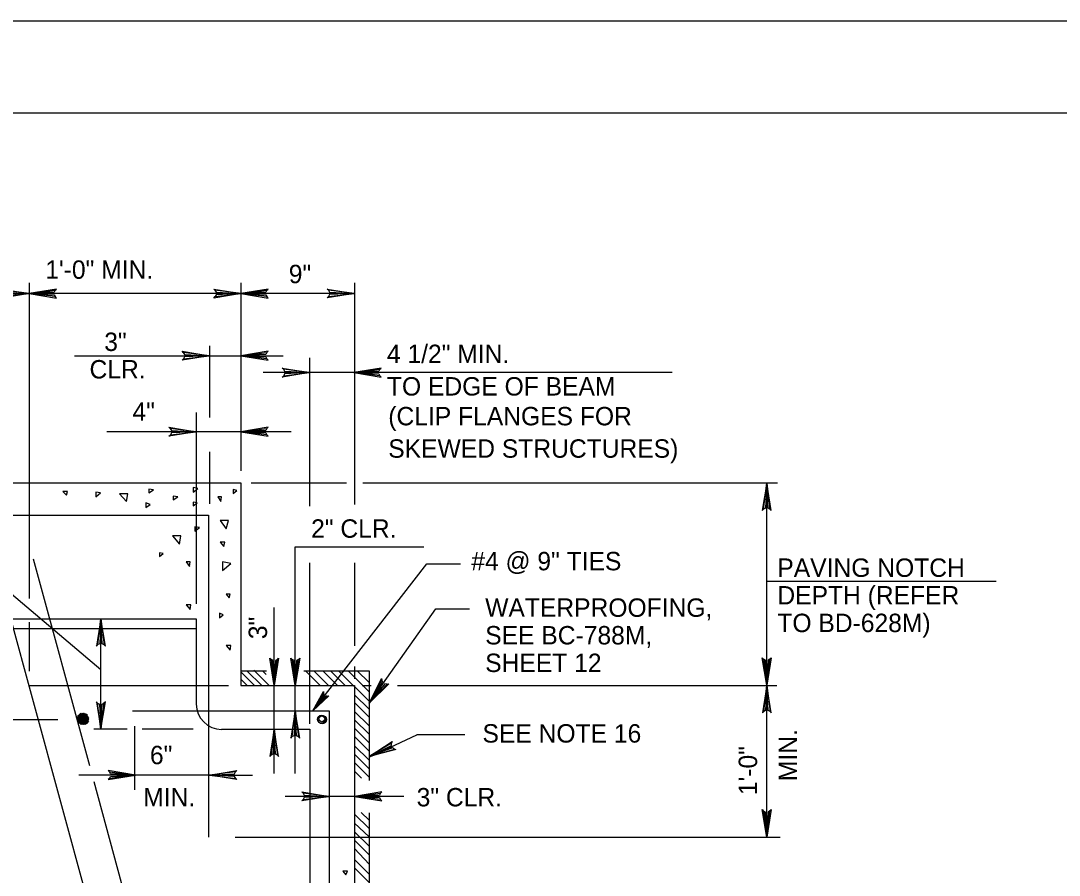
# Model space of a CAD drawing. Extents: x 640009 to 641706, y 298547 to 299735.
# Drawn here: x 640461.6 to 640630.8, y 299595.9 to 299735.2 of the extents above; entities that cross this region are included whole.
import ezdxf

# ---------------------------------------------------------------- set-up
doc = ezdxf.new("R2010")
doc.units = 0
doc.layers.add('1', color=7, linetype='Continuous')
doc.layers.add('PLT-BNDY', color=7, linetype='Continuous')

msp = doc.modelspace()

# ---------------------------------------------------------------- linework, layer by layer
at = {"layer": '1'}
for p, q in [((640049.47, 299720.17), (640835.47, 299720.17)), ((640049.47, 299720.17), (640835.47, 299720.17)), ((640462.97, 299692.45), (640462.97, 299640.98)), ((640497.47, 299692.45), (640497.47, 299661.83)), ((640515.97, 299692.45), (640515.97, 299656.35)), ((640463.05, 299690.72), (640417.97, 299690.72)), ((640497.55, 299690.72), (640463.05, 299690.72)), ((640515.97, 299690.72), (640497.55, 299690.72)), ((640492.34, 299682.18), (640492.34, 299670.5)), ((640470.36, 299680.58), (640504.37, 299680.58)), ((640508.72, 299656.07), (640508.72, 299680.21)), ((640508.72, 299677.84), (640501.09, 299677.84)), ((640567.74, 299677.84), (640508.72, 299677.84)), ((640490.22, 299671.34), (640490.22, 299640.12)), ((640505.68, 299668.19), (640475.66, 299668.19)), ((640492.34, 299664.9), (640492.34, 299656.44)), ((640440.51, 299659.84), (640497.47, 299659.84)), ((640497.47, 299659.84), (640497.47, 299626.84)), ((640499.15, 299659.84), (640514.67, 299659.84)), ((640517.37, 299659.84), (640584.9, 299659.84)), ((640583.15, 299626.84), (640583.15, 299659.84)), ((640453.97, 299654.59), (640492.22, 299654.59)), ((640492.22, 299654.59), (640492.22, 299636.71)), ((640506.34, 299612.48), (640506.34, 299649.43)), ((640506.34, 299649.43), (640527.26, 299649.43)), ((640472.87, 299613.73), (640463.72, 299647.4)), ((640508.72, 299620.58), (640508.72, 299646.82)), ((640509.21, 299622.71), (640527.77, 299646.66)), ((640515.97, 299646.82), (640515.97, 299633.31)), ((640527.77, 299646.66), (640533.23, 299646.66)), ((640583.15, 299643.85), (640620.51, 299643.85)), ((640474.68, 299629.38), (640458.71, 299642.91)), ((640485.09, 299545.46), (640459.59, 299639.34)), ((640502.91, 299612.48), (640502.91, 299639.53)), ((640518.35, 299623.96), (640529.22, 299639.33)), ((640529.22, 299639.33), (640534.7, 299639.33)), ((640458.09, 299637.71), (640490.22, 299637.71)), ((640462.97, 299637.14), (640462.97, 299629.17)), ((640474.68, 299619.71), (640474.68, 299637.71)), ((640490.22, 299637.71), (640490.22, 299623.84)), ((640492.22, 299636.71), (640492.22, 299602.09)), ((640460.48, 299636.09), (640490.22, 299636.09)), ((640515.97, 299629.95), (640515.97, 299627.89)), ((640497.47, 299629.21), (640501.63, 299629.21)), ((640507.72, 299629.21), (640518.35, 299629.21)), ((640518.35, 299629.21), (640518.35, 299611.33)), ((640462.97, 299626.84), (640495.47, 299626.84)), ((640497.47, 299626.84), (640515.97, 299626.84)), ((640515.97, 299626.84), (640515.97, 299545.46)), ((640517.21, 299626.84), (640518.72, 299626.84)), ((640522.99, 299626.84), (640584.78, 299626.84)), ((640583.15, 299602.09), (640583.15, 299626.84)), ((640479.84, 299622.71), (640511.84, 299622.71)), ((640511.84, 299622.71), (640511.84, 299600.84)), ((640467.68, 299621.21), (640434.06, 299621.21)), ((640478.97, 299619.71), (640473.52, 299619.71)), ((640480.22, 299609.84), (640480.22, 299620.21)), ((640489.69, 299619.71), (640481.42, 299619.71)), ((640494.34, 299619.71), (640508.72, 299619.71)), ((640508.72, 299619.71), (640508.72, 299549.34)), ((640518.35, 299615.14), (640526.14, 299618.78)), ((640533.95, 299618.78), (640526.14, 299618.78)), ((640492.59, 299612.21), (640471.09, 299612.21)), ((640487.34, 299560.46), (640473.58, 299611.14)), ((640492.47, 299612.21), (640499.37, 299612.21)), ((640524.04, 299608.75), (640504.71, 299608.75)), ((640518.35, 299606.07), (640518.35, 299525.49)), ((640496.57, 299602.09), (640585.31, 299602.09)), ((640511.84, 299600.84), (640511.84, 299567.59))]:
    msp.add_line(p, q, dxfattribs=at)
for points in [[(640458.76, 299691.25), (640458.93, 299690.93), (640463, 299690.71), (640458.76, 299691.25), (640458.55, 299691.43), (640463, 299690.71), (640458.93, 299690.51), (640458.78, 299690.21), (640463, 299690.71), (640458.55, 299689.98), (640458.78, 299690.21)], [(640467.21, 299691.25), (640467.04, 299690.93), (640462.97, 299690.71), (640467.21, 299691.25), (640467.42, 299691.43), (640462.97, 299690.71), (640467.04, 299690.51), (640467.2, 299690.21), (640462.97, 299690.71), (640467.42, 299689.98), (640467.2, 299690.21)], [(640493.26, 299691.25), (640493.43, 299690.93), (640497.5, 299690.71), (640493.26, 299691.25), (640493.05, 299691.43), (640497.5, 299690.71), (640493.43, 299690.51), (640493.28, 299690.21), (640497.5, 299690.71), (640493.05, 299689.98), (640493.28, 299690.21)], [(640501.71, 299691.25), (640501.54, 299690.93), (640497.47, 299690.71), (640501.71, 299691.25), (640501.92, 299691.43), (640497.47, 299690.71), (640501.54, 299690.51), (640501.7, 299690.21), (640497.47, 299690.71), (640501.92, 299689.98), (640501.7, 299690.21)], [(640511.73, 299691.26), (640511.9, 299690.95), (640515.97, 299690.72), (640511.73, 299691.26), (640511.51, 299691.45), (640515.97, 299690.72), (640511.9, 299690.53), (640511.74, 299690.22), (640515.97, 299690.72), (640511.51, 299690), (640511.74, 299690.22)], [(640488.1, 299681.12), (640488.28, 299680.8), (640492.34, 299680.58), (640488.1, 299681.12), (640487.89, 299681.3), (640492.34, 299680.58), (640488.28, 299680.38), (640488.12, 299680.08), (640492.34, 299680.58), (640487.89, 299679.86), (640488.12, 299680.08)], [(640501.71, 299681.12), (640501.54, 299680.8), (640497.47, 299680.58), (640501.71, 299681.12), (640501.92, 299681.3), (640497.47, 299680.58), (640501.54, 299680.38), (640501.7, 299680.08), (640497.47, 299680.58), (640501.92, 299679.86), (640501.7, 299680.08)], [(640504.43, 299678.36), (640504.61, 299678.04), (640508.68, 299677.82), (640504.43, 299678.36), (640504.22, 299678.55), (640508.68, 299677.82), (640504.61, 299677.62), (640504.45, 299677.32), (640508.68, 299677.82), (640504.22, 299677.1), (640504.45, 299677.32)], [(640520.13, 299678.36), (640519.96, 299678.04), (640515.89, 299677.82), (640520.13, 299678.36), (640520.34, 299678.55), (640515.89, 299677.82), (640519.96, 299677.62), (640520.12, 299677.32), (640515.89, 299677.82), (640520.34, 299677.1), (640520.12, 299677.32)], [(640485.98, 299668.72), (640486.15, 299668.41), (640490.22, 299668.19), (640485.98, 299668.72), (640485.76, 299668.91), (640490.22, 299668.19), (640486.15, 299667.99), (640485.99, 299667.69), (640490.22, 299668.19), (640485.76, 299667.46), (640485.99, 299667.69)], [(640501.71, 299668.72), (640501.54, 299668.41), (640497.47, 299668.19), (640501.71, 299668.72), (640501.92, 299668.91), (640497.47, 299668.19), (640501.54, 299667.99), (640501.7, 299667.69), (640497.47, 299668.19), (640501.92, 299667.46), (640501.7, 299667.69)], [(640583.67, 299655.55), (640583.36, 299655.72), (640583.14, 299659.79), (640583.67, 299655.55), (640583.86, 299655.34), (640583.14, 299659.79), (640582.94, 299655.72), (640582.63, 299655.57), (640583.14, 299659.79), (640582.41, 299655.34), (640582.63, 299655.57)], [(640475.22, 299633.47), (640474.9, 299633.64), (640474.68, 299637.71), (640475.22, 299633.47), (640475.41, 299633.26), (640474.68, 299637.71), (640474.48, 299633.64), (640474.18, 299633.49), (640474.68, 299637.71), (640473.96, 299633.26), (640474.18, 299633.49)], [(640503.44, 299631.08), (640503.13, 299630.91), (640502.91, 299626.84), (640503.44, 299631.08), (640503.63, 299631.29), (640502.91, 299626.84), (640502.71, 299630.91), (640502.4, 299631.06), (640502.91, 299626.84), (640502.18, 299631.29), (640502.4, 299631.06)], [(640506.88, 299631.08), (640506.56, 299630.91), (640506.34, 299626.84), (640506.88, 299631.08), (640507.06, 299631.29), (640506.34, 299626.84), (640506.14, 299630.91), (640505.84, 299631.06), (640506.34, 299626.84), (640505.62, 299631.29), (640505.84, 299631.06)], [(640583.67, 299631.13), (640583.36, 299630.95), (640583.14, 299626.88), (640583.67, 299631.13), (640583.86, 299631.34), (640583.14, 299626.88), (640582.94, 299630.95), (640582.63, 299631.11), (640583.14, 299626.88), (640582.41, 299631.34), (640582.63, 299631.11)], [(640499.69, 299626.84), (640497.47, 299629.06)], [(640498.5, 299626.84), (640497.47, 299627.87)], [(640500.88, 299626.84), (640498.47, 299629.24)], [(640502.07, 299626.84), (640499.6, 299629.31)], [(640501.62, 299628.6), (640501.01, 299629.21)], [(640510.38, 299626.84), (640508.01, 299629.21)], [(640511.74, 299626.84), (640509.37, 299629.21)], [(640513.2, 299626.84), (640510.82, 299629.21)], [(640514.46, 299626.84), (640512.08, 299629.21)], [(640518.46, 299624.14), (640513.39, 299629.21)], [(640518.35, 299625.81), (640514.94, 299629.21)], [(640518.35, 299627.29), (640516.44, 299629.2)], [(640521.29, 299627.07), (640520.93, 299627.11), (640518.35, 299623.96), (640521.29, 299627.07), (640521.57, 299627.12), (640518.35, 299623.96), (640520.59, 299627.36), (640520.44, 299627.67), (640518.35, 299623.96), (640520.4, 299627.98), (640520.44, 299627.67)], [(640583.69, 299622.59), (640583.37, 299622.77), (640583.15, 299626.84), (640583.69, 299622.59), (640583.88, 299622.38), (640583.15, 299626.84), (640582.95, 299622.77), (640582.65, 299622.61), (640583.15, 299626.84), (640582.43, 299622.38), (640582.65, 299622.61)], [(640511.56, 299625.11), (640511.31, 299625.11), (640509.21, 299622.71), (640511.56, 299625.11), (640511.81, 299625.12), (640509.21, 299622.71), (640511.06, 299625.36), (640510.93, 299625.61), (640509.21, 299622.71), (640510.92, 299625.86), (640510.93, 299625.61)], [(640518.35, 299622.95), (640515.97, 299625.33)], [(640474.14, 299623.96), (640474.46, 299623.78), (640474.68, 299619.71), (640474.14, 299623.96), (640473.96, 299624.17), (640474.68, 299619.71), (640474.88, 299623.78), (640475.18, 299623.94), (640474.68, 299619.71), (640475.41, 299624.17), (640475.18, 299623.94)], [(640506.88, 299618.47), (640506.56, 299618.64), (640506.34, 299622.71), (640506.88, 299618.47), (640507.06, 299618.26), (640506.34, 299622.71), (640506.14, 299618.64), (640505.84, 299618.49), (640506.34, 299622.71), (640505.62, 299618.26), (640505.84, 299618.49)], [(640518.35, 299621.69), (640515.97, 299624.07)], [(640470.84, 299621.34), (640471.72, 299622.34)], [(640470.84, 299621.09), (640472.09, 299622.34)], [(640470.84, 299621.09), (640471.97, 299622.34)], [(640470.84, 299621.21), (640471.84, 299622.34)], [(640470.84, 299621.34), (640471.72, 299622.34)], [(640470.84, 299621.46), (640471.59, 299622.34)], [(640470.84, 299621.59), (640471.47, 299622.34)], [(640470.84, 299621.84), (640471.34, 299622.21)], [(640470.97, 299620.84), (640472.34, 299622.21)], [(640470.97, 299620.84), (640472.22, 299622.21)], [(640470.97, 299620.96), (640472.09, 299622.21)], [(640471.09, 299620.71), (640472.47, 299622.09)], [(640471.09, 299620.71), (640472.34, 299622.09)], [(640471.22, 299620.59), (640472.47, 299621.96)], [(640471.22, 299620.59), (640472.47, 299621.96)], [(640471.34, 299620.46), (640472.59, 299621.84)], [(640471.34, 299620.46), (640472.59, 299621.84)], [(640471.34, 299620.59), (640472.59, 299621.84)], [(640471.47, 299620.46), (640472.59, 299621.71)], [(640471.59, 299620.46), (640472.72, 299621.59)], [(640471.72, 299620.46), (640472.72, 299621.46)], [(640471.84, 299620.46), (640472.72, 299621.46)], [(640471.97, 299620.46), (640472.72, 299621.34)], [(640472.09, 299620.46), (640472.72, 299621.09)], [(640518.35, 299620.23), (640515.97, 299622.61)], [(640518.35, 299618.88), (640515.97, 299621.25)], [(640472.34, 299620.59), (640472.59, 299620.84)], [(640503.44, 299615.47), (640503.13, 299615.64), (640502.91, 299619.71), (640503.44, 299615.47), (640503.63, 299615.26), (640502.91, 299619.71), (640502.71, 299615.64), (640502.4, 299615.49), (640502.91, 299619.71), (640502.18, 299615.26), (640502.4, 299615.49)], [(640518.35, 299617.5), (640515.97, 299619.88)], [(640518.35, 299616.15), (640515.97, 299618.54)], [(640522.48, 299616.46), (640522.19, 299616.68), (640518.38, 299615.23), (640522.48, 299616.46), (640522.74, 299616.38), (640518.38, 299615.23), (640522.02, 299617.06), (640522.04, 299617.41), (640518.38, 299615.23), (640522.15, 299617.7), (640522.04, 299617.41)], [(640518.35, 299614.63), (640515.97, 299617)], [(640518.35, 299613.25), (640515.97, 299615.63)], [(640518.35, 299611.88), (640515.97, 299614.25)], [(640476.06, 299611.69), (640476.23, 299612.01), (640480.3, 299612.23), (640476.06, 299611.69), (640475.84, 299611.5), (640480.3, 299612.23), (640476.23, 299612.43), (640476.07, 299612.73), (640480.3, 299612.23), (640475.84, 299612.95), (640476.07, 299612.73)], [(640496.63, 299611.69), (640496.46, 299612.01), (640492.39, 299612.23), (640496.63, 299611.69), (640496.84, 299611.5), (640492.39, 299612.23), (640496.46, 299612.43), (640496.62, 299612.73), (640492.39, 299612.23), (640496.84, 299612.95), (640496.62, 299612.73)], [(640517.12, 299611.73), (640515.97, 299612.88)], [(640507.6, 299609.29), (640507.78, 299608.97), (640511.84, 299608.75), (640507.6, 299609.29), (640507.39, 299609.47), (640511.84, 299608.75), (640507.78, 299608.55), (640507.62, 299608.25), (640511.84, 299608.75), (640507.39, 299608.02), (640507.62, 299608.25)], [(640520.21, 299609.29), (640520.04, 299608.97), (640515.97, 299608.75), (640520.21, 299609.29), (640520.42, 299609.47), (640515.97, 299608.75), (640520.04, 299608.55), (640520.2, 299608.25), (640515.97, 299608.75), (640520.42, 299608.02), (640520.2, 299608.25)], [(640518.35, 299603.5), (640515.97, 299605.88)], [(640518.35, 299604.88), (640517.07, 299606.15)], [(640583.67, 299606.38), (640583.36, 299606.2), (640583.14, 299602.13), (640583.67, 299606.38), (640583.86, 299606.59), (640583.14, 299602.13), (640582.94, 299606.2), (640582.63, 299606.36), (640583.14, 299602.13), (640582.41, 299606.59), (640582.63, 299606.36)], [(640518.35, 299602.15), (640515.97, 299604.38)], [(640518.35, 299600.63), (640515.97, 299603)], [(640518.35, 299599.25), (640515.97, 299601.63)], [(640518.35, 299597.68), (640515.97, 299600.25)], [(640518.35, 299596.1), (640515.97, 299598.47)], [(640518.35, 299594.72), (640515.97, 299597.1)]]:
    msp.add_lwpolyline(points, dxfattribs=at)
for points in [[(640468.47, 299658.46), (640469.09, 299657.84), (640469.22, 299658.46)], [(640473.84, 299657.59), (640474.59, 299658.21), (640473.84, 299658.34)], [(640482.47, 299658.21), (640483.22, 299658.71), (640482.47, 299658.84)], [(640489.72, 299658.34), (640490.47, 299658.96), (640489.72, 299659.09)], [(640496.22, 299658.13), (640496.84, 299658.63), (640496.22, 299658.76)], [(640477.72, 299658.09), (640478.84, 299656.84), (640479.09, 299658.09)], [(640481.97, 299655.84), (640482.72, 299656.34), (640481.97, 299656.59)], [(640486.47, 299657.09), (640487.22, 299657.59), (640486.47, 299657.71)], [(640489.72, 299656.09), (640490.34, 299656.59), (640489.72, 299656.71)], [(640493.72, 299657.59), (640494.22, 299656.84), (640494.34, 299657.59)], [(640494.09, 299653.71), (640495.09, 299652.34), (640495.47, 299653.71)], [(640489.97, 299651.96), (640490.72, 299652.59), (640489.97, 299652.71)], [(640486.34, 299651.21), (640487.47, 299649.84), (640487.72, 299651.21)], [(640494.09, 299650.21), (640494.72, 299649.46), (640494.84, 299650.21)], [(640484.22, 299647.84), (640484.84, 299648.34), (640484.22, 299648.46)], [(640488.59, 299646.96), (640489.09, 299646.21), (640489.22, 299646.96)], [(640494.47, 299645.59), (640495.84, 299646.71), (640494.47, 299646.96)], [(640495.09, 299641.71), (640495.59, 299641.09), (640495.72, 299641.71)], [(640488.59, 299639.96), (640489.22, 299639.21), (640489.34, 299639.96)], [(640493.97, 299637.84), (640494.59, 299638.34), (640493.97, 299638.59)], [(640495.09, 299633.34), (640495.72, 299632.59), (640495.84, 299633.34)], [(640514.09, 299596.59), (640514.59, 299595.96), (640514.84, 299596.59)]]:
    msp.add_lwpolyline(points, close=True, dxfattribs=at)
for centre, radius in [((640510.61, 299621.33), 0.636), ((640510.73, 299621.27), 0.693), ((640510.67, 299621.39), 0.474)]:
    msp.add_circle(centre, radius, dxfattribs=at)
msp.add_arc((640494.34, 299623.8), 4.13, 180, 270, dxfattribs=at)
at = {"layer": 'PLT-BNDY'}
msp.add_lwpolyline([(640009.47, 299735.17), (640850.47, 299735.17), (640850.47, 299141.17), (640009.47, 299141.17)], close=True, dxfattribs=at)

# ---------------------------------------------------------------- texts
at = {"layer": '1'}
for s, p in [('1\'-0" MIN.', (640465.62, 299693.11)), ('9"', (640505.28, 299692.4)), ('3"', (640475.22, 299681.35)), ('4 1/2" MIN.', (640521.27, 299679.38)), ('CLR.', (640472.82, 299676.87)), ('TO EDGE OF BEAM', (640521.27, 299674.09)), ('4"', (640479.82, 299669.97)), ('(CLIP FLANGES FOR', (640521.49, 299669.23)), ('SKEWED STRUCTURES)', (640521.49, 299663.95)), ('2" CLR.', (640508.92, 299650.91)), ('#4 @ 9" TIES', (640535.01, 299645.6)), ('PAVING NOTCH', (640584.87, 299644.53)), ('DEPTH (REFER', (640584.87, 299640.03)), ('WATERPROOFING,', (640537.28, 299638.02)), ('TO BD-628M)', (640584.87, 299635.53)), ('SEE BC-788M,', (640537.28, 299633.52)), ('SHEET 12', (640537.28, 299629.02)), ('SEE NOTE 16', (640536.84, 299617.52)), (' 6"', (640481.55, 299614)), ('MIN.', (640481.56, 299607.13)), ('3" CLR.', (640526.11, 299607.12))]:
    msp.add_text(s, height=3, dxfattribs=at).set_placement(p)
for s, p in [('3"', (640501.74, 299634.38)), ('MIN.', (640588.09, 299611.23)), ('1\'-0"', (640581.57, 299608.96))]:
    msp.add_text(s, height=3, rotation=90, dxfattribs=at).set_placement(p)

doc.saveas('drawing.dxf')
